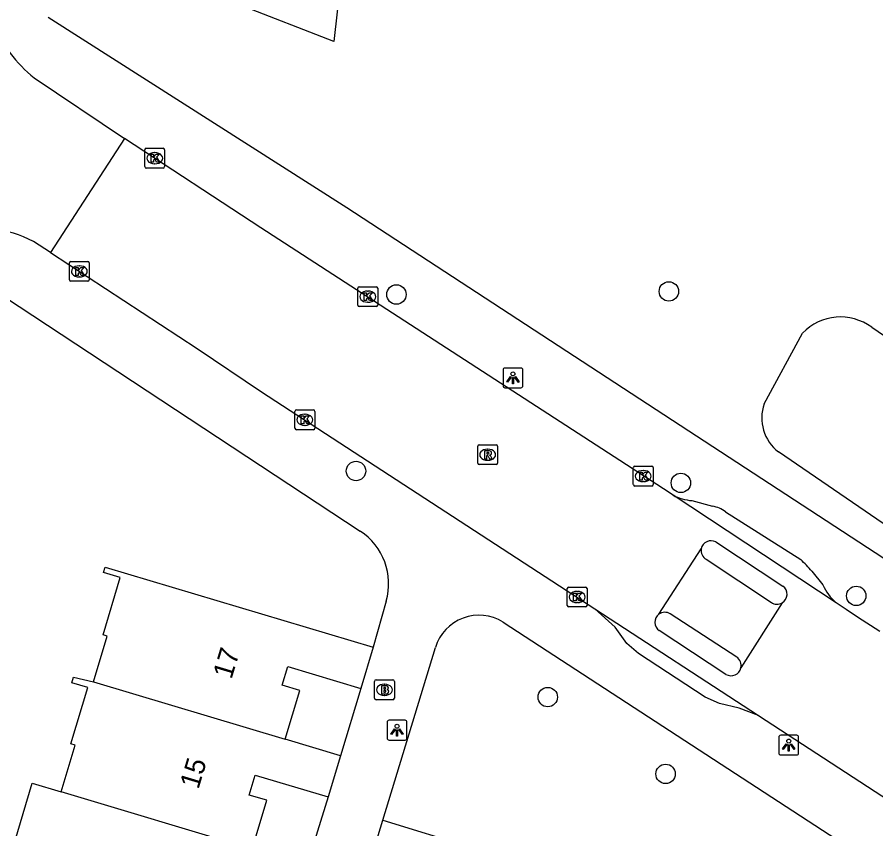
# Model space of a CAD drawing. Extents: x 162186 to 163152, y 385513 to 386513.
# Drawn here: x 162638.71 to 162681.96, y 386298.89 to 386339.79 of the extents above; entities that cross this region are included whole.
import ezdxf

# ---------------------------------------------------------------- set-up
doc = ezdxf.new("R2010")
doc.units = 0
for name, color, linetype in [('IMGEO_Boom', 7, 'Continuous'), ('IMGEO_Brandkraan', 7, 'Continuous'), ('IMGEO_Groenvoorziening', 7, 'Continuous'), ('IMGEO_Kolk', 7, 'Continuous'), ('IMGEO_Lichtpunt', 7, 'Continuous'), ('IMGEO_Meer_plas_ven_vijver', 7, 'Continuous'), ('IMGEO_Pand', 7, 'Continuous'), ('IMGEO_Pand_nummerreeks', 7, 'Continuous'), ('IMGEO_Parkeervlak_open', 7, 'Continuous'), ('IMGEO_Rijbaan_lokaal_gesloten', 7, 'Continuous'), ('IMGEO_Rijbaan_lokaal_open', 7, 'Continuous'), ('IMGEO_Rioolput', 7, 'Continuous'), ('IMGEO_Voetpad_open', 7, 'Continuous')]:
    doc.layers.add(name, color=color, linetype=linetype)

msp = doc.modelspace()

# ---------------------------------------------------------------- linework, layer by layer
at = {"layer": 'IMGEO_Boom'}
for centre in [(162657.81, 386325.813), (162671.533, 386325.969), (162655.774, 386316.92), (162672.137, 386316.32), (162680.972, 386310.628), (162665.432, 386305.529), (162671.369, 386301.658)]:
    msp.add_circle(centre, 0.489, dxfattribs=at)
at = {"layer": 'IMGEO_Brandkraan'}
for p, q in [((162656.782, 386306.396), (162657.634, 386306.396)), ((162656.707, 386305.47), (162656.707, 386306.322)), ((162657.195, 386306.176), (162657.22, 386306.176)), ((162657.708, 386306.322), (162657.708, 386305.47)), ((162657.218, 386305.616), (162657.193, 386305.616)), ((162657.634, 386305.396), (162656.782, 386305.396))]:
    msp.add_line(p, q, dxfattribs=at)
for points in [[(162656.782, 386306.396), (162657.634, 386306.396)], [(162656.707, 386305.47), (162656.707, 386306.322)], [(162657.055, 386306.096), (162657.055, 386305.696), (162657.268, 386305.696)], [(162657.286, 386306.096), (162657.055, 386306.096)], [(162657.234, 386306.015), (162657.18, 386306.015), (162657.18, 386305.939)], [(162657.18, 386305.939), (162657.233, 386305.939)], [(162657.708, 386306.322), (162657.708, 386305.47)], [(162657.242, 386305.863), (162657.18, 386305.863), (162657.18, 386305.782)], [(162657.18, 386305.782), (162657.242, 386305.782)], [(162657.634, 386305.396), (162656.782, 386305.396)]]:
    msp.add_lwpolyline(points, dxfattribs=at)
for centre, radius, start, end in [((162656.784, 386306.32), 0.0765, 91.552, 178.448), ((162656.784, 386306.32), 0.0765, 91.552, 178.448), ((162657.632, 386306.32), 0.0765, 1.552, 88.448), ((162657.632, 386306.32), 0.0765, 1.552, 88.448), ((162657.235, 386305.977), 0.0379, 267.8285, 90.9355), ((162657.29, 386305.951), 0.145, 59.4692, 91.5367), ((162657.315, 386305.998), 0.0922, 285.5137, 58.1501), ((162657.32, 386305.806), 0.105, 301.3115, 78.989), ((162656.784, 386305.472), 0.0765, 181.552, 268.448), ((162656.784, 386305.472), 0.0765, 181.552, 268.448), ((162657.243, 386305.822), 0.0404, 269.8759, 90.5077), ((162657.274, 386305.947), 0.251, 268.6676, 293.5347), ((162657.632, 386305.472), 0.0765, 271.552, 358.448), ((162657.632, 386305.472), 0.0765, 271.552, 358.448)]:
    msp.add_arc(centre, radius, start, end, dxfattribs=at)
for centre, major_axis, ratio, start_param, end_param in [((162657.194, 386305.896), (-0.387, 0.002), 0.722429, 4.712389, 7.853982), ((162657.219, 386305.896), (-0.39, 0.002), 0.717154, 1.570796, 4.712389)]:
    msp.add_ellipse(centre, major_axis=major_axis, ratio=ratio, start_param=start_param, end_param=end_param, dxfattribs=at)
at = {"layer": 'IMGEO_Groenvoorziening'}
msp.add_lwpolyline([(162657.12, 386299.333), (162661.604, 386297.949)], dxfattribs=at)
at = {"layer": 'IMGEO_Kolk'}
for p, q in [((162645.209, 386333.18), (162646.061, 386333.18)), ((162645.134, 386332.254), (162645.134, 386333.106)), ((162645.622, 386332.96), (162645.647, 386332.96)), ((162646.135, 386333.106), (162646.135, 386332.254)), ((162645.645, 386332.4), (162645.62, 386332.4)), ((162646.061, 386332.18), (162645.209, 386332.18)), ((162641.339, 386326.552), (162641.339, 386327.404)), ((162641.414, 386327.478), (162642.266, 386327.478)), ((162641.827, 386327.258), (162641.852, 386327.258)), ((162642.34, 386327.404), (162642.34, 386326.552)), ((162641.85, 386326.698), (162641.825, 386326.698)), ((162642.266, 386326.478), (162641.414, 386326.478)), ((162655.866, 386325.279), (162655.866, 386326.131)), ((162655.941, 386326.205), (162656.793, 386326.205)), ((162656.354, 386325.985), (162656.379, 386325.985)), ((162656.867, 386326.131), (162656.867, 386325.279)), ((162656.377, 386325.425), (162656.352, 386325.425)), ((162656.793, 386325.205), (162655.941, 386325.205)), ((162652.698, 386319.074), (162652.698, 386319.926)), ((162652.773, 386320), (162653.625, 386320)), ((162653.186, 386319.78), (162653.211, 386319.78)), ((162653.699, 386319.926), (162653.699, 386319.074)), ((162653.625, 386319), (162652.773, 386319)), ((162653.209, 386319.22), (162653.184, 386319.22)), ((162669.818, 386317.164), (162670.67, 386317.164)), ((162669.743, 386316.238), (162669.743, 386317.09)), ((162670.231, 386316.944), (162670.256, 386316.944)), ((162670.744, 386317.09), (162670.744, 386316.238)), ((162670.254, 386316.384), (162670.229, 386316.384)), ((162670.67, 386316.164), (162669.818, 386316.164)), ((162666.413, 386310.145), (162666.413, 386310.997)), ((162666.488, 386311.071), (162667.34, 386311.071)), ((162666.901, 386310.851), (162666.926, 386310.851)), ((162667.414, 386310.997), (162667.414, 386310.145)), ((162666.924, 386310.291), (162666.899, 386310.291)), ((162667.34, 386310.071), (162666.488, 386310.071))]:
    msp.add_line(p, q, dxfattribs=at)
for points in [[(162645.209, 386333.18), (162646.061, 386333.18)], [(162645.134, 386332.254), (162645.134, 386333.106)], [(162645.455, 386332.88), (162645.578, 386332.88), (162645.578, 386332.729), (162645.708, 386332.88), (162645.872, 386332.88), (162645.726, 386332.729), (162645.879, 386332.48), (162645.727, 386332.48), (162645.642, 386332.644), (162645.578, 386332.577), (162645.578, 386332.48), (162645.455, 386332.48), (162645.455, 386332.88)], [(162646.135, 386333.106), (162646.135, 386332.254)], [(162646.061, 386332.18), (162645.209, 386332.18)], [(162641.339, 386326.552), (162641.339, 386327.404)], [(162641.414, 386327.478), (162642.266, 386327.478)], [(162641.66, 386327.178), (162641.783, 386327.178), (162641.783, 386327.027), (162641.913, 386327.178), (162642.077, 386327.178), (162641.931, 386327.027), (162642.084, 386326.778), (162641.932, 386326.778), (162641.847, 386326.942), (162641.783, 386326.875), (162641.783, 386326.778), (162641.66, 386326.778), (162641.66, 386327.178)], [(162642.34, 386327.404), (162642.34, 386326.552)], [(162642.266, 386326.478), (162641.414, 386326.478)], [(162655.866, 386325.279), (162655.866, 386326.131)], [(162655.941, 386326.205), (162656.793, 386326.205)], [(162656.187, 386325.905), (162656.31, 386325.905), (162656.31, 386325.754), (162656.44, 386325.905), (162656.604, 386325.905), (162656.458, 386325.754), (162656.611, 386325.505), (162656.459, 386325.505), (162656.374, 386325.669), (162656.31, 386325.602), (162656.31, 386325.505), (162656.187, 386325.505), (162656.187, 386325.905)], [(162656.867, 386326.131), (162656.867, 386325.279)], [(162656.793, 386325.205), (162655.941, 386325.205)], [(162652.698, 386319.074), (162652.698, 386319.926)], [(162652.773, 386320), (162653.625, 386320)], [(162653.699, 386319.926), (162653.699, 386319.074)], [(162653.019, 386319.7), (162653.142, 386319.7), (162653.142, 386319.549), (162653.272, 386319.7), (162653.436, 386319.7), (162653.29, 386319.549), (162653.443, 386319.3), (162653.291, 386319.3), (162653.206, 386319.464), (162653.142, 386319.397), (162653.142, 386319.3), (162653.019, 386319.3), (162653.019, 386319.7)], [(162653.625, 386319), (162652.773, 386319)], [(162669.818, 386317.164), (162670.67, 386317.164)], [(162669.743, 386316.238), (162669.743, 386317.09)], [(162670.064, 386316.864), (162670.187, 386316.864), (162670.187, 386316.713), (162670.317, 386316.864), (162670.481, 386316.864), (162670.335, 386316.713), (162670.488, 386316.464), (162670.336, 386316.464), (162670.251, 386316.628), (162670.187, 386316.561), (162670.187, 386316.464), (162670.064, 386316.464), (162670.064, 386316.864)], [(162670.744, 386317.09), (162670.744, 386316.238)], [(162670.67, 386316.164), (162669.818, 386316.164)], [(162666.413, 386310.145), (162666.413, 386310.997)], [(162666.488, 386311.071), (162667.34, 386311.071)], [(162666.734, 386310.771), (162666.857, 386310.771), (162666.857, 386310.62), (162666.987, 386310.771), (162667.151, 386310.771), (162667.005, 386310.62), (162667.158, 386310.371), (162667.006, 386310.371), (162666.921, 386310.535), (162666.857, 386310.468), (162666.857, 386310.371), (162666.734, 386310.371), (162666.734, 386310.771)], [(162667.414, 386310.997), (162667.414, 386310.145)], [(162667.34, 386310.071), (162666.488, 386310.071)]]:
    msp.add_lwpolyline(points, dxfattribs=at)
for centre, start, end in [((162645.211, 386333.104), 91.552, 178.448), ((162645.211, 386333.104), 91.552, 178.448), ((162646.059, 386333.104), 1.552, 88.448), ((162646.059, 386333.104), 1.552, 88.448), ((162645.211, 386332.256), 181.552, 268.448), ((162645.211, 386332.256), 181.552, 268.448), ((162646.059, 386332.256), 271.552, 358.448), ((162646.059, 386332.256), 271.552, 358.448), ((162641.416, 386327.402), 91.552, 178.448), ((162641.416, 386327.402), 91.552, 178.448), ((162642.264, 386327.402), 1.552, 88.448), ((162642.264, 386327.402), 1.552, 88.448), ((162641.416, 386326.554), 181.552, 268.448), ((162641.416, 386326.554), 181.552, 268.448), ((162642.264, 386326.554), 271.552, 358.448), ((162642.264, 386326.554), 271.552, 358.448), ((162655.943, 386326.129), 91.552, 178.448), ((162655.943, 386326.129), 91.552, 178.448), ((162656.791, 386326.129), 1.552, 88.448), ((162656.791, 386326.129), 1.552, 88.448), ((162655.943, 386325.281), 181.552, 268.448), ((162655.943, 386325.281), 181.552, 268.448), ((162656.791, 386325.281), 271.552, 358.448), ((162656.791, 386325.281), 271.552, 358.448), ((162652.775, 386319.924), 91.552, 178.448), ((162652.775, 386319.924), 91.552, 178.448), ((162653.623, 386319.924), 1.552, 88.448), ((162653.623, 386319.924), 1.552, 88.448), ((162652.775, 386319.076), 181.552, 268.448), ((162652.775, 386319.076), 181.552, 268.448), ((162653.623, 386319.076), 271.552, 358.448), ((162653.623, 386319.076), 271.552, 358.448), ((162669.82, 386317.088), 91.552, 178.448), ((162669.82, 386317.088), 91.552, 178.448), ((162670.668, 386317.088), 1.552, 88.448), ((162670.668, 386317.088), 1.552, 88.448), ((162669.82, 386316.24), 181.552, 268.448), ((162669.82, 386316.24), 181.552, 268.448), ((162670.668, 386316.24), 271.552, 358.448), ((162670.668, 386316.24), 271.552, 358.448), ((162666.49, 386310.995), 91.552, 178.448), ((162666.49, 386310.995), 91.552, 178.448), ((162667.338, 386310.995), 1.552, 88.448), ((162667.338, 386310.995), 1.552, 88.448), ((162666.49, 386310.147), 181.552, 268.448), ((162666.49, 386310.147), 181.552, 268.448), ((162667.338, 386310.147), 271.552, 358.448), ((162667.338, 386310.147), 271.552, 358.448)]:
    msp.add_arc(centre, 0.0765, start, end, dxfattribs=at)
for centre, major_axis, ratio, start_param, end_param in [((162645.621, 386332.68), (-0.387, 0.002), 0.722429, 4.712389, 7.853982), ((162645.646, 386332.68), (-0.39, 0.002), 0.717154, 1.570796, 4.712389), ((162641.826, 386326.978), (-0.387, 0.002), 0.722429, 4.712389, 7.853982), ((162641.851, 386326.978), (-0.39, 0.002), 0.717154, 1.570796, 4.712389), ((162656.353, 386325.705), (-0.387, 0.002), 0.722429, 4.712389, 7.853982), ((162656.378, 386325.705), (-0.39, 0.002), 0.717154, 1.570796, 4.712389), ((162653.185, 386319.5), (-0.387, 0.002), 0.722429, 4.712389, 7.853982), ((162653.21, 386319.5), (-0.39, 0.002), 0.717154, 1.570796, 4.712389), ((162670.23, 386316.664), (-0.387, 0.002), 0.722429, 4.712389, 7.853982), ((162670.255, 386316.664), (-0.39, 0.002), 0.717154, 1.570796, 4.712389), ((162666.9, 386310.571), (-0.387, 0.002), 0.722429, 4.712389, 7.853982), ((162666.925, 386310.571), (-0.39, 0.002), 0.717154, 1.570796, 4.712389)]:
    msp.add_ellipse(centre, major_axis=major_axis, ratio=ratio, start_param=start_param, end_param=end_param, dxfattribs=at)
at = {"layer": 'IMGEO_Lichtpunt'}
for p, q in [((162663.18, 386322.014), (162663.18, 386321.207)), ((162663.18, 386322.014), (162663.18, 386321.207)), ((162664.082, 386322.109), (162663.274, 386322.109)), ((162664.082, 386322.109), (162663.274, 386322.109)), ((162664.176, 386321.207), (162664.176, 386322.014)), ((162664.176, 386321.207), (162664.176, 386322.014)), ((162663.274, 386321.113), (162664.082, 386321.113)), ((162663.274, 386321.113), (162664.082, 386321.113)), ((162657.343, 386304.264), (162657.343, 386303.457)), ((162657.343, 386304.264), (162657.343, 386303.457)), ((162658.245, 386304.359), (162657.437, 386304.359)), ((162658.245, 386304.359), (162657.437, 386304.359)), ((162658.339, 386303.457), (162658.339, 386304.264)), ((162658.339, 386303.457), (162658.339, 386304.264)), ((162657.437, 386303.363), (162658.245, 386303.363)), ((162657.437, 386303.363), (162658.245, 386303.363)), ((162677.073, 386303.514), (162677.073, 386302.707)), ((162677.073, 386303.514), (162677.073, 386302.707)), ((162677.975, 386303.609), (162677.167, 386303.609)), ((162677.975, 386303.609), (162677.167, 386303.609)), ((162678.069, 386302.707), (162678.069, 386303.514)), ((162678.069, 386302.707), (162678.069, 386303.514)), ((162677.167, 386302.613), (162677.975, 386302.613)), ((162677.167, 386302.613), (162677.975, 386302.613))]:
    msp.add_line(p, q, dxfattribs=at)
for points in [[(162663.554, 386321.678), (162663.593, 386321.65), (162663.405, 386321.388), (162663.367, 386321.415), (162663.554, 386321.678)], [(162663.656, 386321.63), (162663.703, 386321.63), (162663.703, 386321.308), (162663.656, 386321.308), (162663.656, 386321.63)], [(162663.766, 386321.65), (162663.804, 386321.677), (162663.991, 386321.415), (162663.952, 386321.387), (162663.766, 386321.65)], [(162657.717, 386303.928), (162657.756, 386303.9), (162657.568, 386303.638), (162657.53, 386303.665), (162657.717, 386303.928)], [(162657.819, 386303.88), (162657.866, 386303.88), (162657.866, 386303.558), (162657.819, 386303.558), (162657.819, 386303.88)], [(162657.929, 386303.9), (162657.967, 386303.927), (162658.154, 386303.665), (162658.115, 386303.637), (162657.929, 386303.9)], [(162677.447, 386303.178), (162677.486, 386303.15), (162677.298, 386302.888), (162677.26, 386302.915), (162677.447, 386303.178)], [(162677.549, 386303.13), (162677.596, 386303.13), (162677.596, 386302.808), (162677.549, 386302.808), (162677.549, 386303.13)], [(162677.659, 386303.15), (162677.697, 386303.177), (162677.884, 386302.915), (162677.845, 386302.887), (162677.659, 386303.15)]]:
    msp.add_lwpolyline(points, dxfattribs=at)
for centre in [(162663.679, 386321.812), (162657.842, 386304.062), (162677.572, 386303.312)]:
    msp.add_circle(centre, 0.0994, dxfattribs=at)
for centre, start, end in [((162663.274, 386322.014), 90, 180), ((162663.274, 386322.014), 90, 180), ((162664.082, 386322.014), 0, 90), ((162664.082, 386322.014), 0, 90), ((162663.274, 386321.207), 180, 270), ((162663.274, 386321.207), 180, 270), ((162664.082, 386321.207), 270, 0), ((162664.082, 386321.207), 270, 360), ((162657.437, 386304.264), 90, 180), ((162657.437, 386304.264), 90, 180), ((162658.245, 386304.264), 0, 90), ((162658.245, 386304.264), 0, 90), ((162657.437, 386303.457), 180, 270), ((162657.437, 386303.457), 180, 270), ((162658.245, 386303.457), 270, 0), ((162658.245, 386303.457), 270, 360), ((162677.167, 386303.514), 90, 180), ((162677.167, 386303.514), 90, 180), ((162677.975, 386303.514), 0, 90), ((162677.975, 386303.514), 0, 90), ((162677.167, 386302.707), 180, 270), ((162677.167, 386302.707), 180, 270), ((162677.975, 386302.707), 270, 0), ((162677.975, 386302.707), 270, 360)]:
    msp.add_arc(centre, 0.0946, start, end, dxfattribs=at)
at = {"layer": 'IMGEO_Meer_plas_ven_vijver'}
for points in [[(162681.75, 386324.159), (162686.871, 386320.653)], [(162676.329, 386320.307), (162678.265, 386323.866)], [(162682.333, 386314.268), (162677.051, 386317.878)]]:
    msp.add_lwpolyline(points, dxfattribs=at)
for centre, radius, start, end in [((162680.173, 386322.044), 2.638, 53.2956, 136.3161), ((162678.398, 386319.6), 2.186, 161.1345, 231.9737)]:
    msp.add_arc(centre, radius, start, end, dxfattribs=at)
at = {"layer": 'IMGEO_Pand'}
for points in [[(162642.559, 386306.303), (162643.248, 386308.605), (162643.038, 386308.668), (162643.902, 386311.553), (162643.063, 386311.804), (162643.146, 386312.081), (162656.644, 386308.039)], [(162656.644, 386308.039), (162656.021, 386305.958)], [(162652.208, 386303.404), (162652.942, 386305.855), (162652.052, 386306.122), (162652.333, 386307.063), (162656.021, 386305.958)], [(162640.924, 386300.762), (162641.628, 386303.109), (162641.408, 386303.175), (162642.259, 386306.017), (162641.462, 386306.255), (162641.544, 386306.528), (162642.559, 386306.303)], [(162642.559, 386306.303), (162652.208, 386303.404)], [(162654.99, 386302.571), (162652.208, 386303.404)], [(162654.99, 386302.571), (162654.37, 386300.5)], [(162650.546, 386297.868), (162651.283, 386300.329), (162650.395, 386300.595), (162650.696, 386301.601), (162654.37, 386300.5)], [(162637.812, 386295.692), (162639.466, 386301.2), (162640.924, 386300.762)], [(162650.546, 386297.868), (162640.924, 386300.762)]]:
    msp.add_lwpolyline(points, dxfattribs=at)
at = {"layer": 'IMGEO_Parkeervlak_open'}
msp.add_lwpolyline([(162661.346, 386398.093), (162654.65, 386338.568), (162649.904, 386340.412)], dxfattribs=at)
at = {"layer": 'IMGEO_Rijbaan_lokaal_gesloten'}
for points in [[(162671.746, 386315.696), (162671.257, 386316.019), (162669.691, 386317.045), (162650.981, 386329.18), (162644.111, 386333.677)], [(162640.381, 386327.933), (162647.775, 386323.092), (162651.022, 386320.911), (162667.801, 386309.976)], [(162679.959, 386310.277), (162671.746, 386315.696)], [(162673.898, 386313.346), (162677.282, 386311.121)], [(162682.166, 386308.827), (162681.036, 386309.556), (162680.468, 386309.941), (162679.959, 386310.277)], [(162667.801, 386309.976), (162676.05, 386304.6)], [(162674.408, 386306.675), (162671.043, 386308.876)], [(162676.05, 386304.6), (162729.502, 386269.766)]]:
    msp.add_lwpolyline(points, dxfattribs=at)
for centre, radius, start, end in [((162673.658, 386312.907), 0.501, 61.3016, 169.7464), ((162676.98, 386310.713), 0.507, 300.7648, 53.5375), ((162671.341, 386309.291), 0.511, 126.7649, 234.3476), ((162674.665, 386307.12), 0.514, 239.957, 346.5132)]:
    msp.add_arc(centre, radius, start, end, dxfattribs=at)
at = {"layer": 'IMGEO_Rijbaan_lokaal_open'}
for points in [[(162639.562, 386336.726), (162644.111, 386333.677)], [(162644.111, 386333.677), (162640.381, 386327.933)], [(162640.381, 386327.933), (162639.525, 386328.477)], [(162671.035, 386309.7), (162673.165, 386312.996)], [(162673.412, 386312.471), (162676.695, 386310.294)], [(162677.24, 386310.277), (162675.165, 386307)], [(162674.949, 386307.548), (162671.601, 386309.73)]]:
    msp.add_lwpolyline(points, dxfattribs=at)
for centre, radius, start, end in [((162643.771, 386342.02), 6.763, 202.1023, 231.5106), ((162637.08, 386324.119), 4.997, 60.7085, 110.3831), ((162673.659, 386312.908), 0.502, 169.8717, 240.52), ((162676.981, 386310.713), 0.507, 235.6846, 300.7421), ((162671.34, 386309.292), 0.509, 59.2382, 126.8299), ((162674.664, 386307.119), 0.515, 346.6483, 56.3766)]:
    msp.add_arc(centre, radius, start, end, dxfattribs=at)
at = {"layer": 'IMGEO_Rioolput'}
for p, q in [((162661.906, 386317.314), (162661.906, 386318.166)), ((162661.981, 386318.24), (162662.833, 386318.24)), ((162662.394, 386318.02), (162662.419, 386318.02)), ((162662.907, 386318.166), (162662.907, 386317.314)), ((162662.833, 386317.24), (162661.981, 386317.24)), ((162662.417, 386317.46), (162662.392, 386317.46))]:
    msp.add_line(p, q, dxfattribs=at)
for points in [[(162661.906, 386317.314), (162661.906, 386318.166)], [(162661.981, 386318.24), (162662.833, 386318.24)], [(162662.907, 386318.166), (162662.907, 386317.314)], [(162662.495, 386317.938), (162662.243, 386317.94), (162662.243, 386317.54)], [(162662.243, 386317.54), (162662.367, 386317.54), (162662.367, 386317.702), (162662.378, 386317.702)], [(162662.421, 386317.859), (162662.367, 386317.859), (162662.367, 386317.778)], [(162662.367, 386317.778), (162662.419, 386317.778)], [(162662.425, 386317.673), (162662.496, 386317.54), (162662.636, 386317.54), (162662.571, 386317.666)], [(162662.833, 386317.24), (162661.981, 386317.24)]]:
    msp.add_lwpolyline(points, dxfattribs=at)
for centre, radius, start, end in [((162661.983, 386318.164), 0.0765, 91.552, 178.448), ((162661.983, 386318.164), 0.0765, 91.552, 178.448), ((162662.831, 386318.164), 0.0765, 1.552, 88.448), ((162662.831, 386318.164), 0.0765, 1.552, 88.448), ((162662.377, 386317.649), 0.0533, 26.0293, 88.6989), ((162662.403, 386317.967), 0.19, 274.7715, 282.9687), ((162662.427, 386317.763), 0.0964, 77.0061, 93.1865), ((162662.441, 386317.82), 0.0378, 276.6634, 79.6772), ((162662.494, 386317.828), 0.109, 350.3612, 89.416), ((162662.492, 386317.828), 0.112, 277.5842, 350.9817), ((162662.476, 386317.613), 0.108, 29.5134, 73.7905), ((162661.983, 386317.316), 0.0765, 181.552, 268.448), ((162661.983, 386317.316), 0.0765, 181.552, 268.448), ((162662.831, 386317.316), 0.0765, 271.552, 358.448), ((162662.831, 386317.316), 0.0765, 271.552, 358.448)]:
    msp.add_arc(centre, radius, start, end, dxfattribs=at)
for centre, major_axis, ratio, start_param, end_param in [((162662.393, 386317.74), (-0.387, 0.002), 0.722429, 4.712389, 7.853982), ((162662.418, 386317.74), (-0.39, 0.002), 0.717154, 1.570796, 4.712389)]:
    msp.add_ellipse(centre, major_axis=major_axis, ratio=ratio, start_param=start_param, end_param=end_param, dxfattribs=at)
at = {"layer": 'IMGEO_Voetpad_open'}
for points in [[(162640.264, 386339.786), (162655.308, 386330.194), (162684.39, 386311.194)], [(162634.389, 386324.676), (162634.496, 386324.876), (162634.621, 386325.066), (162634.763, 386325.244), (162634.92, 386325.408), (162635.091, 386325.558), (162635.274, 386325.692), (162635.469, 386325.809), (162635.673, 386325.908), (162635.886, 386325.988), (162636.105, 386326.049), (162636.328, 386326.091), (162636.554, 386326.112), (162636.781, 386326.113), (162637.008, 386326.093), (162637.232, 386326.054), (162637.451, 386325.995), (162637.664, 386325.916), (162637.869, 386325.818), (162638.065, 386325.703), (162655.987, 386313.896)], [(162672.696, 386315.426), (162673.733, 386315.14)], [(162674.381, 386314.859), (162678.181, 386312.462)], [(162678.73, 386311.867), (162679.288, 386311.188)], [(162657.293, 386310.356), (162656.644, 386308.039)], [(162676.05, 386304.6), (162675.07, 386304.977), (162674.076, 386305.206), (162673.36, 386305.528), (162670.002, 386307.721), (162669.416, 386308.234), (162668.834, 386309.047), (162667.801, 386309.976)], [(162663.186, 386309.305), (162691.308, 386290.98)], [(162657.12, 386299.333), (162659.773, 386308.026)], [(162656.021, 386305.958), (162654.99, 386302.571)], [(162654.37, 386300.5), (162653.3, 386297.043)], [(162653.011, 386285.784), (162657.12, 386299.333)]]:
    msp.add_lwpolyline(points, dxfattribs=at)
for centre, radius, start, end in [((162672.918, 386318.015), 2.598, 243.1789, 265.0897), ((162673.58, 386313.899), 1.251, 50.1567, 82.9562), ((162654.234, 386311.238), 3.184, 343.9122, 56.5885), ((162669.809, 386304.187), 11.771, 40.7267, 44.668), ((162681.568, 386312.165), 2.481, 203.1927, 229.5545), ((162661.97, 386307.356), 2.297, 58.0433, 163.043)]:
    msp.add_arc(centre, radius, start, end, dxfattribs=at)

# ---------------------------------------------------------------- texts
at = {"layer": 'IMGEO_Pand_nummerreeks'}
for s, p in [('17', (162649.501, 386306.394)), ('15', (162647.835, 386300.851))]:
    msp.add_text(s, height=1, rotation=73.2662, dxfattribs=at).set_placement(p)

doc.saveas('drawing.dxf')
